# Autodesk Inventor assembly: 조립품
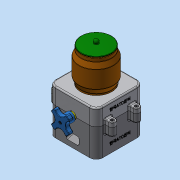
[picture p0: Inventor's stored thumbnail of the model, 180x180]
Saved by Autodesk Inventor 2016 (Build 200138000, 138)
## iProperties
Created: 2018-01
Part Number: 조립품
Material: 일반
Document SubType Name: Assembly
Designer: Administrator
Author: Administrator
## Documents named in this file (9)
- C:\Users\Administrator\Desktop\480108V1024\조립품.iam
- C:\Users\Administrator\Desktop\480108V1024\1.본체.ipt
- C:\Users\Administrator\Desktop\480108V1024\본체커버.ipt
- C:\Users\Administrator\Desktop\480108V1024\볼트 M3x12.ipt
- C:\Users\Administrator\Desktop\480108V1024\볼트 M4x12.ipt
- C:\Users\Administrator\Desktop\480108V1024\용기.ipt
- C:\Users\Administrator\Desktop\480108V1024\용기캡.ipt
- C:\Users\Administrator\Desktop\480108V1024\핸들.ipt
- C:\Users\Administrator\Desktop\480108V1024\핸들축.ipt
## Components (3 placed, 3 different names)
1. 1.본체:1 — 각도:2
2. 핸들:1 — 각도:1
3. 핸들축:1 — 각도:1, 각도:2
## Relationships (2: Angle 2)
- 각도:1 [Angle]: 핸들:1 ↔ 핸들축:1
- 각도:2 [Angle]: 1.본체:1 ↔ 핸들축:1
